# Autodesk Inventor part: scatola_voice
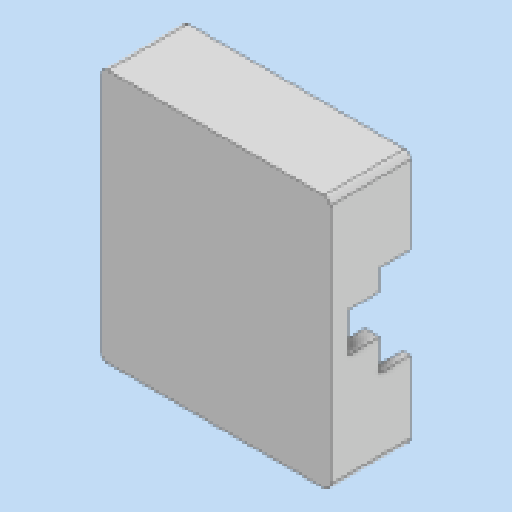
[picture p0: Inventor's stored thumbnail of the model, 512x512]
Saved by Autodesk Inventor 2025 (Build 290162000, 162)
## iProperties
Created: 2025-03
Part Number: scatola_voice
Material: Generico
Document SubType Name: Modeling
Designer: Ryzen5700u
Density: 1 g/cm^3
Appearance: Default
Author: Ryzen5700u
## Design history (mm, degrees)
sketch "Schizzo1"
  geometry: L1 (47.588, 12.346)-(-26.412, 12.346); L2 (-26.412, 12.346)-(-26.412, -69.654); L3 (-26.412, -69.654)-(47.588, -69.654); L4 (47.588, -69.654)-(47.588, 12.346); 1 further point
  constraints: 8 end point, 2 parallel, 1 horizontal, 1 perpendicular
  dimensions: "d0" = 74 distance of L3.end L2.end; "d1" = 82 distance of L2.end L1.end
extrude "Estrusione1" new body sketch "Schizzo1" distance "d2" = 6; taper "d3" = 0 deg
sketch "Schizzo2"
  geometry: L1 (-21.088, -17.654)-(-40.088, -17.654) reference; L2 (-40.088, -41.654)-(-21.088, -41.654) reference; L3 (-36.088, -41.854)-(-23.088, -41.854); L4 (-17.088, -17.454)-(-36.088, -17.454); L5 (-7.088, -14.654)-(-23.588, -14.654) reference; L6 (-3.088, -14.854)-(-19.588, -14.854); L7 (-47.588, -69.654)-(-47.588, 12.346) reference; L8 (-17.088, -17.454)-(-47.588, -17.454); L9 (-47.588, -17.454)-(-47.588, -14.885); L10 (-47.588, -14.885)-(-17.088, -14.885); L11 (-17.088, -14.885)-(-17.088, -17.454); L12 (-42.588, -20.154)-(-42.588, -23.654) reference; L13 (-42.588, -35.654)-(-42.588, -39.154) reference; L14 (-42.788, -20.154)-(-42.788, -22.534); L15 (-42.788, -22.534)-(-47.588, -22.534); L16 (-47.588, -22.534)-(-47.588, -17.454); L17 (-47.588, -17.454)-(-42.788, -17.454); L18 (-42.788, -17.454)-(-42.788, -22.534); L19 (-42.788, -37.278)-(-47.588, -37.278); L20 (-47.588, -37.278)-(-47.588, -44.457); L21 (-47.588, -44.457)-(-42.788, -44.457); L22 (-42.788, -44.457)-(-42.788, -37.278); L23 (-23.088, -41.854)-(-42.788, -41.854); L24 (-42.788, -41.854)-(-42.788, -44.457); L25 (-42.788, -44.457)-(-23.088, -44.457); L26 (-23.088, -44.457)-(-23.088, -41.854); L27 (-18.588, -39.154)-(-18.588, -20.154) reference; L28 (-18.388, -37.154)-(-18.388, -20.787); L29 (-18.388, -20.787)-(-16.888, -20.787); L30 (-16.888, -20.787)-(-16.888, -38.829); L31 (-16.888, -38.829)-(-18.388, -38.829); L32 (-18.388, -38.829)-(-18.388, -20.787); 15 further points
  constraints: 50 end point, 15 parallel, 5 horizontal, 5 perpendicular, 3 point on line
  dimensions: "d5" = 0.2 distance between parallel lines of L3 L2; "d6" = 0.2 distance between parallel lines of L1 L4; "d7" = 0.2 distance between parallel lines of L5 L6; "d8" = 0.2 distance between parallel lines of L12 L14; "d9" = 0.2 distance between parallel lines of L27 L28; "d10" = 1.5 distance of L30.end L31.end
extrude "Estrusione2" join sketch "Schizzo2" distance "d11" = 10; taper "d12" = 0 deg
extrude "Estrusione3" join sketch "Schizzo3" distance "d19" = 4; taper "d20" = 0 deg
fillet "Raccordo1" dims "d21" = 1
sketch "Schizzo4"
  geometry: C1 r 2.4 at (-16.588, -10.654) reference; C2 r 2.4 at (-16.588, 5.346) reference; C3 r 2.3 at (-16.588, 5.346); C4 r 2.3 at (-16.588, -10.654); 1 further point
  constraints: 2 centre point, 2 coincident
  dimensions: "d22" = 4.6 diameter of C3; "d23" = 4.6 diameter of C4
  node "Riferimento13"
  node "Riferimento14"
node "Piano di lavoro1"
extrude "Estrusione4" join sketch "Schizzo4" stored distance "d24" = 4; taper "d25" = 0 deg
sketch "Schizzo5"
  geometry: L1 (-42.788, -22.534)-(-47.588, -22.534) reference; L2 (-47.588, -37.278)-(-47.588, -22.534) reference; L3 (-47.588, -37.278)-(-42.788, -37.278) reference; L4 (-42.788, -37.278)-(-42.788, -41.854) reference; L5 (-42.788, -41.854)-(-23.088, -41.854) reference; L6 (-23.088, -41.854)-(-23.088, -44.457) reference; L7 (-23.088, -44.457)-(-47.588, -44.457) reference; L8 (-47.588, -69.654)-(-47.588, -44.457) reference; L9 (26.412, -69.654)-(-47.588, -69.654) reference; L10 (26.412, 12.346)-(26.412, -69.654) reference; L11 (-47.588, 12.346)-(26.412, 12.346) reference; L12 (-47.588, -14.885)-(-47.588, 12.346) reference; L13 (-47.588, -14.885)-(-17.088, -14.885) reference; L14 (-17.088, -14.885)-(-17.088, -17.454) reference; L15 (-17.088, -17.454)-(-42.788, -17.454) reference; L16 (-42.788, -17.454)-(-42.788, -22.534) reference; L17 (-16.888, -38.829)-(-18.388, -38.829) reference; L18 (-18.388, -38.829)-(-18.388, -20.787) reference; L19 (-18.388, -20.787)-(-16.888, -20.787) reference; L20 (-16.888, -20.787)-(-16.888, -38.829) reference; L21 (-47.588, 12.346)-(26.412, 12.346) reference; L22 (-47.588, 12.346)-(26.412, 12.346); L23 (26.412, 12.346)-(26.412, 9.846); L24 (26.412, 9.846)-(-47.588, 9.846); L25 (-47.588, 9.846)-(-47.588, 12.346); L26 (26.412, 12.346)-(23.912, 12.346); L27 (23.912, 12.346)-(23.912, -69.654); L28 (23.912, -69.654)-(26.412, -69.654); L29 (26.412, -69.654)-(26.412, 12.346); L30 (-47.588, 12.346)-(-45.088, 12.346); L31 (-45.088, 12.346)-(-45.088, -14.885); L32 (-45.088, -14.885)-(-47.588, -14.885); L33 (-47.588, -14.885)-(-47.588, 12.346); L34 (-47.588, -44.457)-(-45.088, -44.457); L35 (-45.088, -44.457)-(-45.088, -69.654); L36 (-45.088, -69.654)-(-47.588, -69.654); L37 (-47.588, -69.654)-(-47.588, -44.457); L38 (-47.588, -69.654)-(-16.588, -69.654); L39 (-16.588, -69.654)-(-16.588, -67.154); L40 (-16.588, -67.154)-(-47.588, -67.154); L41 (-47.588, -67.154)-(-47.588, -69.654); L42 (26.412, -69.654)-(-47.588, -69.654) reference; L43 (26.412, -69.654)-(20.412, -69.654); L44 (20.412, -69.654)-(20.412, -67.154); L45 (20.412, -67.154)-(26.412, -67.154); L46 (26.412, -67.154)-(26.412, -69.654); L47 (-45.088, 3.846)-(-39.088, 9.846); L48 (-45.088, 3.846)-(-36.603, 3.846); L49 (17.912, 9.846)-(23.912, 5.346); L50 (20.412, -67.154)-(23.912, -62.487); L51 (-39.088, -67.154)-(-45.088, -62.654); C1 r 2.3 at (-16.588, -10.654) reference; C2 r 2.3 at (-16.588, 5.346) reference; C3 r 2.5 at (17.371, -20.575) reference; C4 r 2.5 at (-13.667, -65.279) reference; C5 r 2.5 at (17.371, -65.279) reference; C6 r 2.5 at (-13.667, -20.575) reference; 8 further points
  constraints: 58 end point, 12 parallel, 12 point on line, 8 perpendicular, 7 horizontal, 1 equal length
  dimensions: "d26" = 2.5 distance of L22.end L23.end; "d27" = 2.5 distance of L28.end L27.end; "d28" = 2.5 distance of L31.end L32.end; "d29" = 2.5 distance of L35.end L36.end; "d30" = 2.5 distance of L39.end L38.end; "d31" = 6 distance of L44.end L45.end; "d34" = 45 deg angle of L48 L47; "d35" = 6 distance from line of L31 L47.end; "d36" = 6 distance from line of L27 L49.start; "d37" = 6 distance from line of L35 L51.start
extrude "Estrusione5" join sketch "Schizzo5" distance "d32" = 20; taper "d33" = 0 deg
fillet "Raccordo2" dims "d38" = 2
sketch "Schizzo6"
  geometry: L1 (-47.588, 10.346)-(-47.588, -14.885) reference; L2 (24.412, 12.346)-(-45.588, 12.346) reference; L3 (26.412, -67.654)-(26.412, 10.346) reference; L4 (-45.588, -69.654)-(-16.588, -69.654) reference; L5 (-47.588, -44.457)-(-47.588, -67.654) reference; 5 further points
  dimensions: "d39" = 3 distance from line of L1 point (-44.588, 9.346); "d40" = 3 distance from line of L2 point (-44.588, 9.346); "d41" = 3 distance from line of L2 point (23.412, 9.346); "d42" = 3 distance from line of L3 point (23.412, 9.346); "d43" = 3 distance from line of L4 point (-44.588, -66.654); "d44" = 3 distance from line of L5 point (-44.588, -66.654); "d45" = 3 distance from line of L3 point (23.412, -66.654)
hole "Foro1" sketch "Schizzo6" at (-44.588, 9.346), (23.412, 9.346), (-44.588, -66.654), (23.412, -66.654) diameter "d46" = 2; stored, may be unused: countersink angle "d50" = 90 deg, drill point angle "d52" = 118 deg; dims "d47" = 6, "d48" = 4, "d49" = 2, "d51" = 8
sketch "Schizzo7"
  geometry: L1 (-17.088, -14.885)-(-45.088, -14.885) reference; L2 (-47.588, -44.457)-(-45.088, -44.457) reference; L3 (-45.088, -14.885)-(-47.588, -14.885); L4 (-47.588, -14.885)-(-47.588, -44.457); L5 (-47.588, -44.457)-(-45.088, -44.457); L6 (-45.088, -44.457)-(-45.088, -14.885); 2 further points
  constraints: 8 end point, 2 parallel, 1 horizontal, 1 perpendicular
extrude "Estrusione6" join sketch "Schizzo7" stored distance "d53" = 20; taper "d54" = 0 deg
node "Solido1"
node "Riferimento1"
node "Riferimento2"
node "Riferimento3"
node "Riferimento4"
node "Riferimento5"
node "Riferimento6"
node "Linea chiusa proiettata2"
other parameters: "d13" = 3, "d14" = 3, "d15" = 3, "d16" = 3, "d17" = 4.6, "d18" = 4.6
